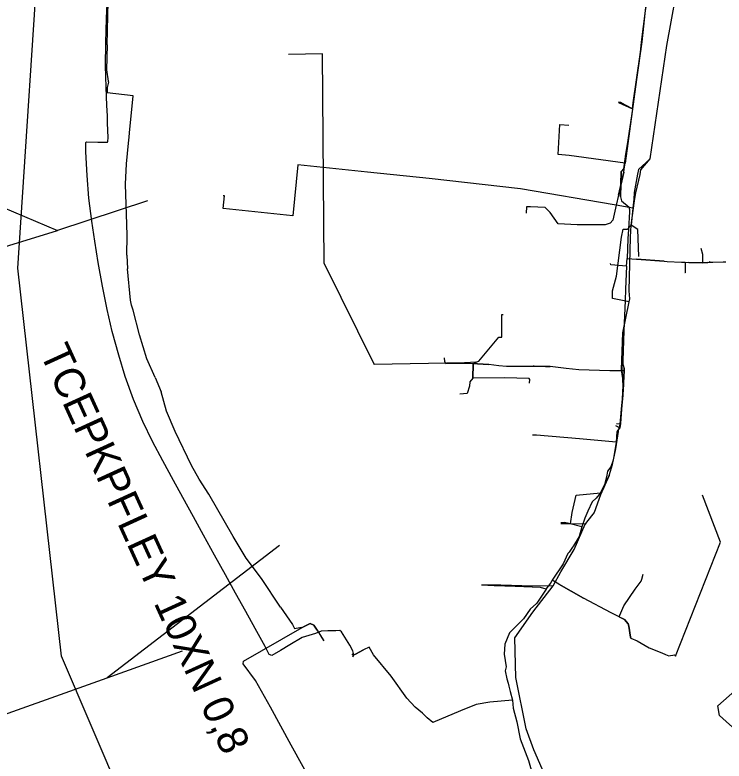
# Model space of a CAD drawing. Extents: x -555222 to -543220, y -1067119 to -1030889.
# Drawn here: x -550759.6 to -550478.9, y -1043967.2 to -1043672 of the extents above; entities that cross this region are included whole.
import ezdxf

# ---------------------------------------------------------------- set-up
doc = ezdxf.new("R2010")
doc.units = 0
for name, color, linetype in [('07_ELEKTRO', 7, 'Continuous'), ('07_OCH_P A POPISY TI', 7, 'Continuous'), ('07_SDĚLOVACÍ', 7, 'Continuous'), ('07_VODOVOD', 7, 'Continuous')]:
    doc.layers.add(name, color=color, linetype=linetype)

msp = doc.modelspace()

# ---------------------------------------------------------------- linework, layer by layer
at = {"layer": '07_ELEKTRO'}
for points in [[(-550786.51, -1043738.86), (-550742.76, -1043757.24)], [(-550707.18, -1043745.55), (-550742.76, -1043757.24)], [(-550763.82, -1043763.75), (-550742.76, -1043757.24)], [(-550654.87, -1043881.95), (-550723.1, -1043934.34)], [(-550723.1, -1043934.34), (-550693.28, -1043923.64)], [(-550779.08, -1043954.21), (-550723.1, -1043934.34)]]:
    msp.add_lwpolyline(points, dxfattribs=at)
at = {"layer": '07_SDĚLOVACÍ'}
for p, q in [((-550723.16, -1043683.8), (-550722.78, -1043666.62)), ((-550723.16, -1043683.8), (-550723.39, -1043693.66)), ((-550723.39, -1043693.66), (-550722.7, -1043698.19)), ((-550722.62, -1043698.57), (-550723.15, -1043700.74)), ((-550722.7, -1043698.19), (-550722.62, -1043698.57)), ((-550723.15, -1043700.74), (-550723.11, -1043702.78)), ((-550712.76, -1043704.06), (-550723.11, -1043702.78)), ((-550714.22, -1043718.69), (-550712.76, -1043704.06)), ((-550714.62, -1043722.7), (-550714.35, -1043720.38)), ((-550714.35, -1043720.38), (-550714.22, -1043718.69)), ((-550715.41, -1043730.95), (-550714.62, -1043722.7)), ((-550715.88, -1043738.92), (-550715.41, -1043730.95)), ((-550715.36, -1043754.98), (-550715.88, -1043738.92)), ((-550715.26, -1043759.32), (-550715.36, -1043754.98)), ((-550715.36, -1043767.02), (-550715.26, -1043759.32)), ((-550715.36, -1043767.02), (-550715.01, -1043772.46)), ((-550713.82, -1043784.89), (-550715.01, -1043772.46)), ((-550713.53, -1043786.87), (-550713.82, -1043784.89)), ((-550712.78, -1043788.79), (-550713.53, -1043786.87)), ((-550710.32, -1043798.57), (-550712.78, -1043788.79)), ((-550707.41, -1043808.08), (-550710.32, -1043798.57)), ((-550704.14, -1043815.42), (-550707.41, -1043808.08)), ((-550704.14, -1043815.42), (-550701.72, -1043821.1)), ((-550699.68, -1043828.72), (-550701.72, -1043821.1)), ((-550696.24, -1043836.84), (-550699.68, -1043828.72)), ((-550689.77, -1043850.23), (-550696.24, -1043836.84)), ((-550686.72, -1043855.74), (-550689.77, -1043850.23)), ((-550682.84, -1043861.62), (-550686.72, -1043855.74)), ((-550673.28, -1043878.31), (-550682.84, -1043861.62)), ((-550668.08, -1043886.93), (-550673.28, -1043878.31)), ((-550662.05, -1043894.94), (-550668.08, -1043886.93)), ((-550654.53, -1043906.36), (-550662.05, -1043894.94)), ((-550654.53, -1043906.36), (-550649.76, -1043913.15)), ((-550642.79, -1043912.86), (-550645.45, -1043914.08)), ((-550642.79, -1043912.86), (-550645.45, -1043914.08)), ((-550642.79, -1043912.86), (-550645.45, -1043914.08)), ((-550641.3, -1043913.42), (-550642.79, -1043912.86)), ((-550641.3, -1043913.42), (-550642.79, -1043912.86)), ((-550641.3, -1043913.42), (-550642.79, -1043912.86)), ((-550649.76, -1043913.15), (-550648.94, -1043914.72)), ((-550648.94, -1043914.72), (-550645.45, -1043914.08)), ((-550639.94, -1043915.39), (-550641.3, -1043913.42)), ((-550639.94, -1043915.39), (-550641.3, -1043913.42)), ((-550639.94, -1043915.39), (-550641.3, -1043913.42)), ((-550639.94, -1043915.39), (-550637.46, -1043919.49)), ((-550639.94, -1043915.39), (-550637.34, -1043919.7)), ((-550639.94, -1043915.39), (-550637.36, -1043919.66))]:
    msp.add_line(p, q, dxfattribs=at)
for points in [[(-550515.19, -1043709.11), (-550514.86, -1043706.81), (-550512.04, -1043686.77), (-550511.54, -1043682.8), (-550510, -1043670.37), (-550507.29, -1043652.84), (-550505.35, -1043638.76), (-550505.28, -1043637.03), (-550505.5, -1043635.41), (-550505.3, -1043633.61), (-550504.17, -1043630.11), (-550503.05, -1043626.44)], [(-550508.2, -1043728.98), (-550501.54, -1043684.13), (-550496.1, -1043654.47), (-550494.06, -1043639.7), (-550492.72, -1043631.47)], [(-550505.22, -1043638.12), (-550507.65, -1043652.92), (-550509.9, -1043667.76), (-550511.43, -1043682.69), (-550513.56, -1043697.54), (-550518.13, -1043730.65)], [(-550723.03, -1043711.85), (-550723.26, -1043707.78), (-550723.51, -1043700.58), (-550723.81, -1043692.07), (-550723.7, -1043683.09), (-550723.38, -1043673.39), (-550723.05, -1043664.39), (-550722.67, -1043656.36), (-550722.64, -1043652.38)], [(-550511.54, -1043682.8), (-550512.04, -1043686.77)], [(-550637.18, -1043770.4), (-550637.88, -1043687.36), (-550651.4, -1043687.65)], [(-550515.19, -1043709.11), (-550517.91, -1043707.63), (-550519.8, -1043706.6), (-550520.54, -1043706.5), (-550520.68, -1043706.63)], [(-550520.68, -1043706.63), (-550515.19, -1043709.11)], [(-550515.22, -1043709.31), (-550517.23, -1043723.27), (-550517.9, -1043727.05), (-550518.74, -1043732.86), (-550519.66, -1043733.96), (-550519.96, -1043743.97), (-550519.46, -1043745.52), (-550516.5, -1043748.1), (-550516.42, -1043748.56)], [(-550515.19, -1043709.11), (-550515.22, -1043709.31)], [(-550626.16, -1043925.38), (-550625.55, -1043924.68), (-550625.88, -1043923.63), (-550627.08, -1043921.31), (-550630.33, -1043916.06), (-550631.02, -1043915.53), (-550632.61, -1043915.71), (-550635.79, -1043915.71), (-550638.34, -1043915.82), (-550640.59, -1043916.79), (-550645.97, -1043918.32), (-550650.83, -1043921.26), (-550654.52, -1043923.48), (-550658, -1043925.45), (-550658.97, -1043925.08), (-550660.56, -1043921.94), (-550664.47, -1043914.83), (-550668.23, -1043908.08), (-550672.3, -1043900.8), (-550676.3, -1043893.52), (-550680.64, -1043885.76), (-550684.97, -1043877.88), (-550688.91, -1043870.61), (-550693.15, -1043862.97), (-550696.9, -1043856.18), (-550701.13, -1043848.4), (-550705.14, -1043840.79), (-550708.98, -1043832.83), (-550712.72, -1043824.21), (-550716.03, -1043815.1), (-550718.55, -1043806.67), (-550721.17, -1043797.29), (-550723.17, -1043788.59), (-550724.98, -1043779.3), (-550726.63, -1043769.9), (-550728, -1043761.45), (-550729.18, -1043753.66), (-550730.37, -1043744.5), (-550731.02, -1043735.49), (-550731.59, -1043726.14), (-550731.58, -1043722.49), (-550731.35, -1043722.2), (-550726.81, -1043722.28), (-550723.02, -1043722.37), (-550722.79, -1043722.13), (-550722.71, -1043720.48), (-550723.01, -1043714.83), (-550723.03, -1043711.85)], [(-550518.13, -1043730.65), (-550540.25, -1043727.6), (-550544.6, -1043727.27), (-550543.91, -1043715.38), (-550540.3, -1043715.59)], [(-550517.23, -1043723.27), (-550517.9, -1043727.05)], [(-550508.2, -1043728.98), (-550512.79, -1043733.12), (-550513.18, -1043734.97), (-550514.5, -1043742.28), (-550514.69, -1043744.88)], [(-550512.18, -1043735.11), (-550511.8, -1043733.27), (-550508.2, -1043728.98)], [(-550522.42, -1043747.19), (-550559.49, -1043740.79), (-550595.7, -1043736.74), (-550620.12, -1043734.19), (-550647.62, -1043731.32), (-550649.57, -1043751.54), (-550677.24, -1043748.54), (-550676.7, -1043743.63), (-550677.19, -1043743.57)], [(-550520.71, -1043743.3), (-550518.62, -1043734.2), (-550518.45, -1043732.98)], [(-550518.62, -1043734.2), (-550518.45, -1043732.98), (-550518.13, -1043730.65)], [(-550518.62, -1043734.2), (-550520.71, -1043743.3), (-550521.64, -1043747.32)], [(-550519.96, -1043743.97), (-550519.66, -1043733.96)], [(-550513.9, -1043742.35), (-550512.18, -1043735.11)], [(-550515.67, -1043755.2), (-550514.37, -1043745.49), (-550513.9, -1043742.35)], [(-550521.64, -1043747.32), (-550523, -1043753.18), (-550524.03, -1043754.45), (-550525.98, -1043755.04), (-550537.02, -1043755.09), (-550544.58, -1043754.62), (-550547.77, -1043750.19), (-550549.68, -1043748.2), (-550555.55, -1043747.93), (-550557.14, -1043747.89), (-550557.31, -1043750.43)], [(-550521.64, -1043747.32), (-550522.42, -1043747.19)], [(-550515.03, -1043748.47), (-550521.64, -1043747.32)], [(-550519.46, -1043745.52), (-550516.5, -1043748.1)], [(-550514.69, -1043744.88), (-550515.03, -1043748.47)], [(-550516.39, -1043749.95), (-550516.78, -1043756.75), (-550516.95, -1043760.61), (-550517.31, -1043768.37)], [(-550516.42, -1043748.56), (-550516.34, -1043749), (-550516.39, -1043749.95)], [(-550515.03, -1043748.47), (-550515.67, -1043755.2)], [(-550519.52, -1043759.94), (-550518.87, -1043756.78), (-550517.16, -1043756.8), (-550515.67, -1043755.2)], [(-550516.49, -1043785.49), (-550516.25, -1043784.39), (-550516.45, -1043781.16), (-550516.02, -1043759.94), (-550515.67, -1043755.2)], [(-550512.67, -1043767.59), (-550513.05, -1043756.95), (-550515.67, -1043755.2)], [(-550516.78, -1043756.75), (-550516.95, -1043760.61)], [(-550516.49, -1043785.49), (-550523.11, -1043784.14), (-550523.05, -1043781.12), (-550521.45, -1043775.36), (-550519.52, -1043759.94)], [(-550487.33, -1043770.07), (-550487.27, -1043766.79), (-550487.92, -1043764.41)], [(-550517.49, -1043771.44), (-550517.31, -1043768.37)], [(-550517.31, -1043768.37), (-550513.57, -1043768.65), (-550502.6, -1043769.46), (-550501.41, -1043769.52), (-550495.71, -1043769.8), (-550494.36, -1043769.87)], [(-550637.18, -1043770.4), (-550617.38, -1043810.26)], [(-550517.49, -1043771.44), (-550523.73, -1043770.89), (-550523.92, -1043770.34)], [(-550502.6, -1043769.46), (-550513.57, -1043768.65)], [(-550501.41, -1043769.52), (-550495.71, -1043769.8)], [(-550494.36, -1043769.87), (-550494.29, -1043773.36), (-550494.28, -1043774.05), (-550494.48, -1043774.08)], [(-550494.36, -1043769.87), (-550492.86, -1043769.91), (-550487.33, -1043770.07)], [(-550494.36, -1043769.87), (-550494.29, -1043773.36)], [(-550487.33, -1043770.07), (-550492.86, -1043769.91)], [(-550487.33, -1043770.07), (-550485.35, -1043769.92), (-550484.62, -1043769.86)], [(-550485.35, -1043769.92), (-550487.33, -1043770.07)], [(-550484.62, -1043769.86), (-550484.6, -1043769.47)], [(-550484.62, -1043769.86), (-550483.33, -1043769.83), (-550479.31, -1043769.74), (-550478.18, -1043769.72)], [(-550483.33, -1043769.83), (-550479.31, -1043769.74)], [(-550517.49, -1043771.44), (-550517.9, -1043780.54), (-550518.1, -1043784.99), (-550518.63, -1043797.02), (-550518.96, -1043808.82)], [(-550517.9, -1043780.54), (-550518.1, -1043784.99)], [(-550518.93, -1043797.73), (-550516.49, -1043785.49)], [(-550577.16, -1043809.41), (-550576, -1043809.06), (-550568.13, -1043799.46), (-550566.88, -1043799.49), (-550566.92, -1043790.59), (-550566.42, -1043790.59)], [(-550519.39, -1043826.49), (-550518.64, -1043818.6), (-550519.54, -1043812.32), (-550518.93, -1043797.73)], [(-550518.93, -1043797.73), (-550519.34, -1043812.32), (-550519.04, -1043818.56), (-550519.39, -1043826.49)], [(-550581.68, -1043809.68), (-550617.38, -1043810.26)], [(-550578.27, -1043810.04), (-550583.13, -1043809.97), (-550589.06, -1043810.03), (-550589.51, -1043809.14), (-550589.59, -1043807.72)], [(-550581.41, -1043809.68), (-550581.68, -1043809.68)], [(-550577.16, -1043809.41), (-550581.41, -1043809.68)], [(-550578.27, -1043810.04), (-550577.16, -1043809.41)], [(-550518.96, -1043808.82), (-550519, -1043810.15), (-550518.43, -1043811.95), (-550518.47, -1043812.76)], [(-550578.4, -1043815.77), (-550578.27, -1043810.04)], [(-550578.27, -1043810.04), (-550578.4, -1043815.77)], [(-550554.23, -1043811.1), (-550565.01, -1043811.16), (-550568.09, -1043810.86), (-550571.99, -1043810.37), (-550576.58, -1043810.06), (-550578.27, -1043810.04)], [(-550576.58, -1043810.06), (-550571.99, -1043810.37)], [(-550554.23, -1043811.1), (-550554.23, -1043810.71)], [(-550518.47, -1043812.76), (-550519.66, -1043812.76), (-550524.18, -1043812.78), (-550536.45, -1043812.42), (-550541.45, -1043811.9), (-550547.82, -1043811.09), (-550549.58, -1043811.08), (-550554.23, -1043811.1)], [(-550549.58, -1043811.08), (-550547.82, -1043811.09)], [(-550518.47, -1043812.76), (-550518.43, -1043811.95)], [(-550555.98, -1043817.75), (-550555.8, -1043816.24), (-550556.07, -1043815.89), (-550565.84, -1043815.6), (-550578.4, -1043815.77)], [(-550519.66, -1043812.76), (-550524.18, -1043812.78)], [(-550518.47, -1043812.76), (-550518.86, -1043819.98), (-550519.03, -1043822.56), (-550519.34, -1043826.47), (-550519.63, -1043829.78), (-550519.86, -1043833.67), (-550520.13, -1043835.4)], [(-550518.86, -1043819.98), (-550518.47, -1043812.76)], [(-550578.4, -1043815.77), (-550579.53, -1043817.13), (-550579.69, -1043818.92), (-550580.64, -1043821.81), (-550583.52, -1043822.04)], [(-550519.03, -1043822.56), (-550519.34, -1043826.47)], [(-550520.1, -1043833.88), (-550519.39, -1043826.49)], [(-550519.63, -1043829.78), (-550519.86, -1043833.67)], [(-550521.86, -1043834.42), (-550520.13, -1043835.4)], [(-550520.13, -1043835.4), (-550520.92, -1043836.24), (-550521.3, -1043837.01), (-550521.61, -1043841.03)], [(-550520.1, -1043833.88), (-550521.5, -1043833.76)], [(-550520.75, -1043836.84), (-550520.67, -1043836.34), (-550520.17, -1043834.58), (-550520.1, -1043833.88)], [(-550521.61, -1043841.03), (-550536.13, -1043839.74), (-550553.14, -1043838.22), (-550554.76, -1043838.32)], [(-550524.41, -1043854.25), (-550523.14, -1043849.83), (-550521.82, -1043843.7), (-550520.75, -1043836.84)], [(-550521.3, -1043837.01), (-550521.61, -1043841.03)], [(-550521.61, -1043841.03), (-550522.02, -1043843.45)], [(-550522.02, -1043843.45), (-550522.82, -1043848.17), (-550523.71, -1043850.8), (-550525.01, -1043852.48), (-550525.35, -1043854.06), (-550526.53, -1043858.92), (-550527.68, -1043860.92), (-550529.58, -1043863.16), (-550531.17, -1043864.65), (-550532.81, -1043868.31), (-550534.06, -1043871.16), (-550535.22, -1043874.49)], [(-550539.72, -1043873.35), (-550539.02, -1043868.92), (-550537.52, -1043861.97), (-550527.82, -1043861.08), (-550524.41, -1043854.25)], [(-550524.41, -1043854.25), (-550527.79, -1043861.85), (-550530.32, -1043868.92), (-550533.37, -1043872.76)], [(-550480.28, -1043880.65), (-550487.48, -1043862.08)], [(-550531.17, -1043864.65), (-550532.81, -1043868.31)], [(-550543.54, -1043892.31), (-550538.23, -1043883.51), (-550533.92, -1043873.46)], [(-550535.22, -1043874.49), (-550540.36, -1043873.19), (-550542.08, -1043872.83), (-550543.52, -1043873.01)], [(-550539.72, -1043873.35), (-550543.52, -1043873.4)], [(-550533.92, -1043873.46), (-550539.72, -1043873.35)], [(-550535.22, -1043874.49), (-550536.28, -1043878.32), (-550538.55, -1043882.05), (-550538.87, -1043882.61)], [(-550535.22, -1043874.49), (-550536.28, -1043878.32)], [(-550533.37, -1043872.76), (-550533.92, -1043873.46)], [(-550538.87, -1043882.61), (-550540.26, -1043884.61), (-550540.72, -1043885.12), (-550542.65, -1043889.24), (-550546.93, -1043895.65)], [(-550498.18, -1043925.79), (-550480.28, -1043880.65)], [(-550546.54, -1043897.91), (-550543.54, -1043892.31)], [(-550520.44, -1043910.22), (-550520.13, -1043909.52), (-550518.53, -1043905.86), (-550514.1, -1043899.18), (-550511.75, -1043896.05), (-550511.53, -1043895.29), (-550511, -1043893.25)], [(-550520.13, -1043909.52), (-550518.53, -1043905.86), (-550514.1, -1043899.18), (-550511.75, -1043896.05), (-550511.53, -1043895.29)], [(-550546.54, -1043897.91), (-550554.78, -1043898.01), (-550567.3, -1043897.68), (-550574.92, -1043897.59)], [(-550549.34, -1043899.25), (-550551.53, -1043898.62), (-550564.88, -1043898.05), (-550565.7, -1043898.02), (-550569.94, -1043897.84), (-550574.92, -1043897.64)], [(-550565.7, -1043898.02), (-550569.94, -1043897.84)], [(-550554.59, -1043908.25), (-550546.54, -1043897.91)], [(-550549.34, -1043899.25), (-550547.51, -1043896.8)], [(-550547.51, -1043896.8), (-550546.93, -1043895.65)], [(-550520.44, -1043910.22), (-550523.57, -1043908.58), (-550534.57, -1043902.71), (-550544.38, -1043897.18), (-550546.93, -1043895.65)], [(-550544.38, -1043897.18), (-550534.57, -1043902.71)], [(-550549.34, -1043899.25), (-550552.99, -1043904.69), (-550553.12, -1043904.82)], [(-550553.12, -1043904.82), (-550555.64, -1043907.09), (-550558.29, -1043910.92), (-550563.8, -1043916.51), (-550565.64, -1043920.98), (-550566.01, -1043924.92), (-550565.13, -1043929.97), (-550565.53, -1043931.56), (-550564.92, -1043934.69), (-550564.36, -1043936.45), (-550564.07, -1043937.62)], [(-550561.71, -1043918.47), (-550554.59, -1043908.25)], [(-550640.77, -1043978.07), (-550650.22, -1043960.89), (-550658.46, -1043945.96), (-550664.35, -1043935.38), (-550669.31, -1043928.71), (-550669.14, -1043927.73), (-550646.85, -1043914.92), (-550645.45, -1043914.08), (-550642.79, -1043912.86), (-550641.3, -1043913.42), (-550639.94, -1043915.39), (-550637.36, -1043919.66)], [(-550558.29, -1043910.92), (-550563.8, -1043916.51)], [(-550520.44, -1043910.22), (-550519.35, -1043910.73), (-550518.27, -1043911.23), (-550516.88, -1043912.95), (-550516.66, -1043913.82), (-550515.97, -1043918.2), (-550515.79, -1043918.62), (-550513.31, -1043919.65), (-550508.56, -1043922.37), (-550503.56, -1043924.37), (-550502.11, -1043925.01)], [(-550515.79, -1043918.62), (-550515.97, -1043918.2), (-550516.66, -1043913.82), (-550516.88, -1043912.95), (-550518.27, -1043911.23), (-550519.35, -1043910.73)], [(-550561.4, -1043934.21), (-550561.71, -1043918.47)], [(-550562.71, -1043943.17), (-550571.7, -1043943.92), (-550576.99, -1043944.82), (-550583.2, -1043947.31), (-550594.16, -1043951.99), (-550596.39, -1043950.15), (-550598.34, -1043948.3), (-550601.13, -1043945.88), (-550604.52, -1043942.28), (-550610.65, -1043933.67), (-550617.71, -1043925.17), (-550619.4, -1043922.18), (-550621.6, -1043923.24), (-550624.87, -1043924.91), (-550625.31, -1043925.19), (-550625.46, -1043925.23), (-550626.04, -1043926.14)], [(-550624.87, -1043924.91), (-550621.6, -1043923.24)], [(-550502.11, -1043925.01), (-550500.84, -1043925.57), (-550500.11, -1043925.5), (-550499.14, -1043925.27)], [(-550499.14, -1043925.27), (-550498.6, -1043925.15), (-550498.36, -1043925.16), (-550498.18, -1043925.79)], [(-550564.92, -1043934.69), (-550564.36, -1043936.45)], [(-550557.28, -1043954.53), (-550561.4, -1043934.21)], [(-550564.07, -1043937.62), (-550563.57, -1043939.67), (-550562.71, -1043943.17)], [(-550437.89, -1043995.85), (-550438.71, -1043994.12), (-550444.59, -1043984.43), (-550455.24, -1043973.05), (-550473, -1043956.23), (-550480.75, -1043949.18), (-550481.36, -1043945.38), (-550472.4, -1043937.46)], [(-550562.71, -1043943.17), (-550562.42, -1043946.3), (-550560.97, -1043951.65), (-550559.67, -1043958.43), (-550556.27, -1043966.97), (-550553.8, -1043975.83), (-550550.96, -1043983.4), (-550547.93, -1043989.41), (-550546.96, -1043990.84), (-550542.58, -1043997.19), (-550529.87, -1044011.67)], [(-550596.39, -1043950.15), (-550598.34, -1043948.3)], [(-550554.18, -1043962.74), (-550557.28, -1043954.53)], [(-550526.37, -1044011.24), (-550529.63, -1044008.68), (-550531.34, -1044006.74), (-550533.35, -1044005.6), (-550542.03, -1044000.63), (-550543.01, -1043988.43), (-550554.18, -1043962.74)]]:
    msp.add_lwpolyline(points, dxfattribs=at)
at = {"layer": '07_VODOVOD'}
msp.add_lwpolyline([(-550680.05, -1044068.39), (-550741.21, -1043925.77), (-550758.46, -1043772.18), (-550749.05, -1043629.57), (-550683.19, -1043477.54), (-550620.43, -1043319.91), (-550507.52, -1043124), (-550432.01, -1042330.28)], dxfattribs=at)

# ---------------------------------------------------------------- texts
at = {"layer": '07_OCH_P A POPISY TI'}
msp.add_text('TCEPKPFLEY 10XN 0,8', height=12, rotation=294.516, dxfattribs=at).set_placement((-550749.96, -1043805.63))

doc.saveas('drawing.dxf')
